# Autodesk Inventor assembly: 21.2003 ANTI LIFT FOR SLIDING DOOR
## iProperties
Created: 2007-05
Part Number: 21.2003 ANTI LIFT FOR SLIDING DOOR
Document SubType Name: Assembly
Designer: Andy Moles
Author: Andy Moles
